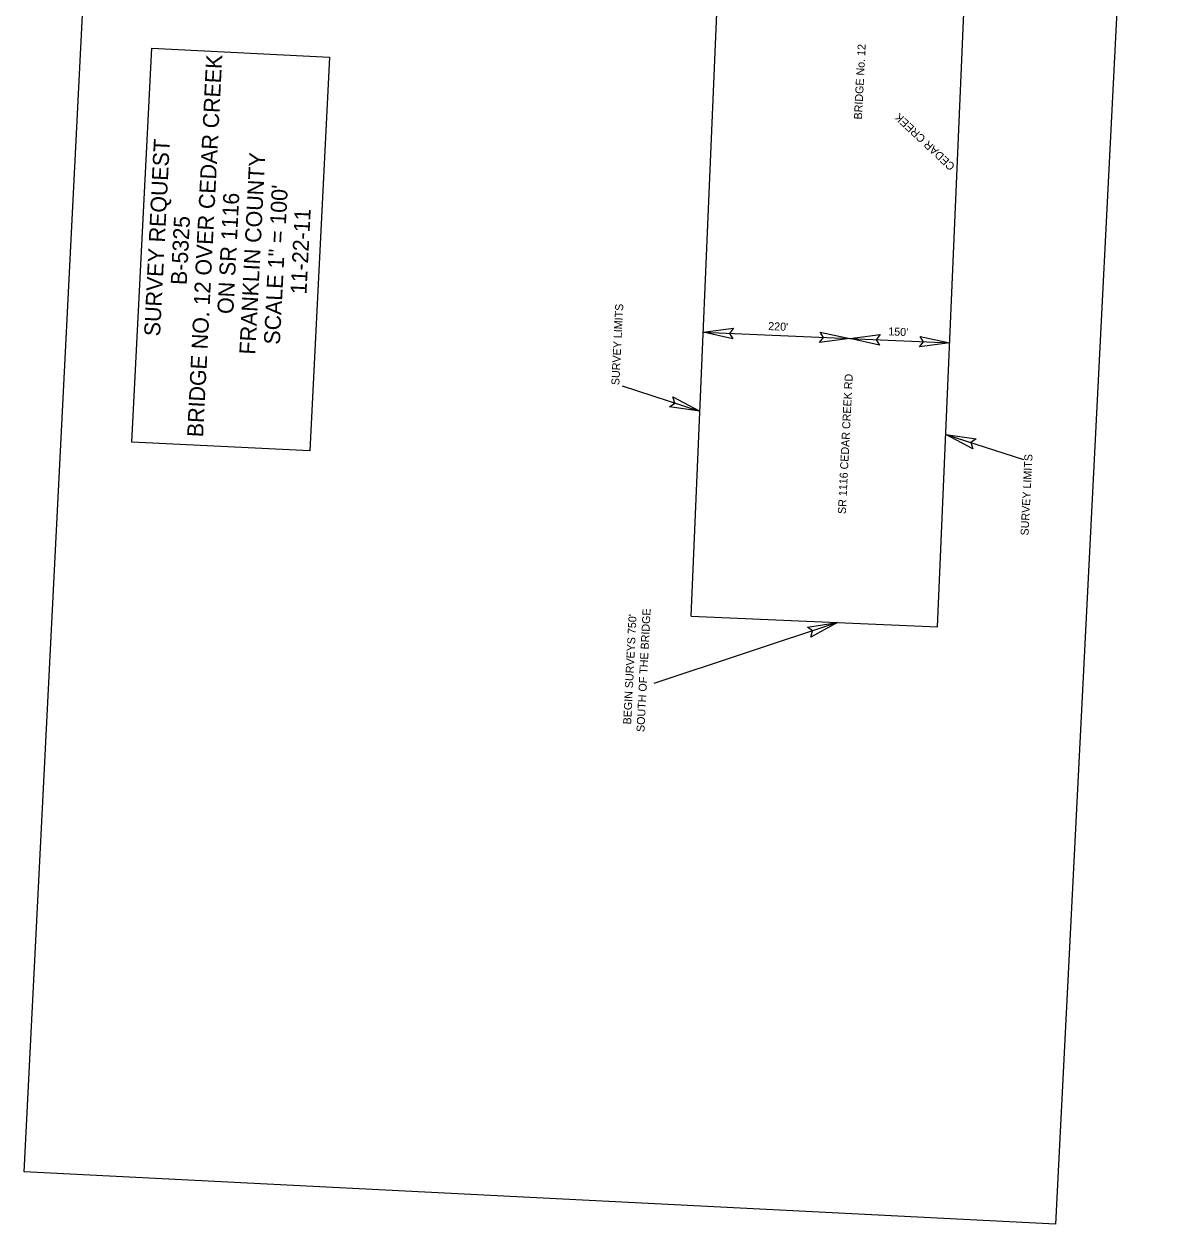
# Model space of a CAD drawing. Extents: x 2166842 to 2171409, y 841731 to 901457.
# Drawn here: x 2166842 to 2168559, y 841731 to 843530 of the extents above; entities that cross this region are included whole.
import ezdxf

# ---------------------------------------------------------------- set-up
doc = ezdxf.new("R2010")
doc.units = 0
doc.layers.add('Default', color=7, linetype='Continuous')
doc.layers.add('Prop Terminator CELL', color=7, linetype='Continuous')

msp = doc.modelspace()

# ---------------------------------------------------------------- linework, layer by layer
at = {"layer": 'Default'}
for p, q in [((2167842.5, 842642.3), (2167885.2, 843637.6)), ((2168212.2, 842626.4), (2168254.8, 843621.8)), ((2167860.8, 843068.1), (2168080.6, 843058.7)), ((2168080.6, 843058.7), (2168230.4, 843052.3)), ((2167739.3, 842987.6), (2167855.7, 842950)), ((2168224.5, 842914.8), (2168340.9, 842877.2)), ((2167842.5, 842642.3), (2168062.3, 842632.9)), ((2168062.3, 842632.9), (2167786.5, 842541.5)), ((2168062.3, 842632.9), (2168212.2, 842626.4))]:
    msp.add_line(p, q, dxfattribs=at)
for points in [[(2167012.6, 845180.7), (2168559.1, 845102.7), (2168389, 841731), (2166842.5, 841809)], [(2167004.2, 842903.6), (2167034, 843494), (2167300.6, 843480.6), (2167270.8, 842890.2)]]:
    msp.add_lwpolyline(points, close=True, dxfattribs=at)
at = {"layer": 'Prop Terminator CELL'}
for points in [[(2167905.4, 843058.5), (2167860.8, 843068.1), (2167906.3, 843074.2), (2167900.2, 843066.4)], [(2168035.9, 843068.4), (2168080.6, 843058.7), (2168035, 843052.7), (2168041.1, 843060.4)], [(2168125.2, 843049), (2168080.6, 843058.7), (2168126.1, 843064.8), (2168120, 843057)], [(2168185.8, 843062), (2168230.4, 843052.3), (2168184.9, 843046.2), (2168191, 843054)], [(2167815.3, 842971.2), (2167855.7, 842950), (2167810.2, 842956.3), (2167818.1, 842962.1)], [(2168265, 842893.6), (2168224.5, 842914.8), (2168270.1, 842908.5), (2168262.1, 842902.7)], [(2168017.2, 842626.1), (2168062.3, 842632.9), (2168021.9, 842611), (2168024.8, 842620.4)]]:
    msp.add_lwpolyline(points, close=True, dxfattribs=at)

# ---------------------------------------------------------------- texts
at = {"layer": 'Default'}
for s, height, rotation, p in [('BRIDGE No. 12', 12, 87.1116, (2168098.7, 843387)), ('BRIDGE NO. 12 OVER CEDAR CREEK', 24, 87.1116, (2167110.9, 842910.4)), ('CEDAR CREEK', 12, 136.6611, (2168239.2, 843318.2)), ('SURVEY REQUEST', 24, 87.1116, (2167046.4, 843061.7)), ('FRANKLIN COUNTY', 24, 87.1116, (2167189.2, 843034.3)), ('ON SR 1116', 24, 87.1116, (2167156.2, 843095.1)), ('SCALE 1" = 100\'', 24, 87.1116, (2167226, 843049.2)), ('B-5325', 24, 87.1116, (2167086.3, 843138.6)), ('11-22-11', 24, 87.1116, (2167265.9, 843124.7)), ('SURVEY LIMITS', 12, 87.1116, (2167734.9, 842988.6)), ("220'", 12, 357.5461, (2167958, 843071.5)), ("150'", 12, 357.5461, (2168138, 843063.6)), ('SR 1116 CEDAR CREEK RD', 12, 87.1116, (2168074.5, 842795.4)), ('SURVEY LIMITS', 12, 87.1116, (2168348.4, 842763.2)), ("BEGIN SURVEYS 750'", 12, 87.1116, (2167752.6, 842479.9)), ('SOUTH OF THE BRIDGE', 12, 87.1116, (2167772.6, 842468.5))]:
    msp.add_text(s, height=height, rotation=rotation, dxfattribs=at).set_placement(p)

doc.saveas('drawing.dxf')
